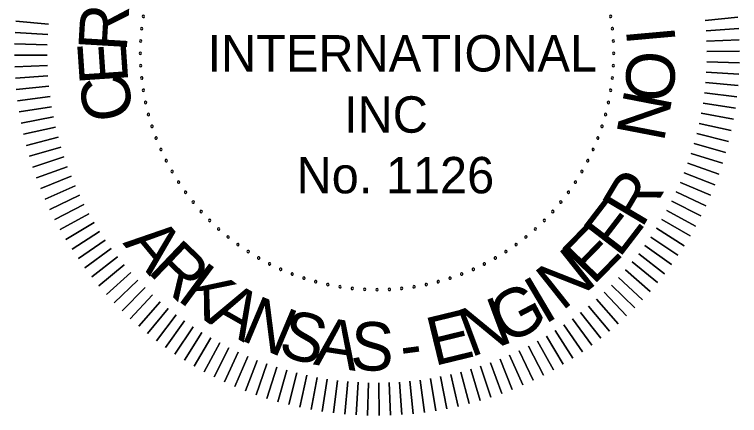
# Model space of a CAD drawing. Extents: x -712 to 3943, y 73 to 2823.
# Drawn here: x 2762.9 to 2970.3, y 202.1 to 316.9 of the extents above; entities that cross this region are included whole.
import ezdxf

# ---------------------------------------------------------------- set-up
doc = ezdxf.new("R2010")
doc.units = 0
doc.layers.add('G-ANNO-TEXT', color=7, linetype='Continuous')

msp = doc.modelspace()

# ---------------------------------------------------------------- linework, layer by layer
at = {"layer": 'G-ANNO-TEXT'}
for points in [[(2969.83, 316.1), (2960.53, 315.17)], [(2960.53, 315.17), (2969.83, 316.1)], [(2772.67, 314.12), (2763.35, 314.95)], [(2763.35, 314.95), (2772.67, 314.12)], [(2772.45, 311.16), (2763.12, 311.7)], [(2763.12, 311.7), (2772.45, 311.16)], [(2970.11, 312.85), (2960.78, 312.21)], [(2960.78, 312.21), (2970.11, 312.85)], [(2970.28, 309.6), (2960.93, 309.25)], [(2960.93, 309.25), (2970.28, 309.6)], [(2772.33, 308.2), (2762.98, 308.45)], [(2762.98, 308.45), (2772.33, 308.2)], [(2772.3, 305.24), (2762.95, 305.19)], [(2762.95, 305.19), (2772.3, 305.24)], [(2970.35, 306.34), (2961, 306.29)], [(2961, 306.29), (2970.35, 306.34)], [(2970.31, 303.09), (2960.97, 303.33)], [(2960.97, 303.33), (2970.31, 303.09)], [(2772.36, 302.28), (2763.02, 301.93)], [(2763.02, 301.93), (2772.36, 302.28)], [(2772.52, 299.32), (2763.19, 298.68)], [(2763.19, 298.68), (2772.52, 299.32)], [(2970.18, 299.83), (2960.84, 300.37)], [(2960.84, 300.37), (2970.18, 299.83)], [(2969.94, 296.58), (2960.63, 297.41)], [(2960.63, 297.41), (2969.94, 296.58)], [(2772.77, 296.36), (2763.46, 295.43)], [(2763.46, 295.43), (2772.77, 296.36)], [(2773.11, 293.42), (2763.84, 292.2)], [(2763.84, 292.2), (2773.11, 293.42)], [(2969.6, 293.34), (2960.32, 294.46)], [(2960.32, 294.46), (2969.6, 293.34)], [(2773.54, 290.49), (2764.32, 288.97)], [(2764.32, 288.97), (2773.54, 290.49)], [(2969.16, 290.11), (2959.92, 291.53)], [(2959.92, 291.53), (2969.16, 290.11)], [(2968.62, 286.9), (2959.42, 288.6)], [(2959.42, 288.6), (2968.62, 286.9)], [(2774.07, 287.57), (2764.89, 285.77)], [(2764.89, 285.77), (2774.07, 287.57)], [(2774.69, 284.67), (2765.57, 282.58)], [(2765.57, 282.58), (2774.69, 284.67)], [(2967.98, 283.71), (2958.84, 285.7)], [(2958.84, 285.7), (2967.98, 283.71)], [(2967.23, 280.54), (2958.16, 282.81)], [(2958.16, 282.81), (2967.23, 280.54)], [(2775.4, 281.79), (2766.35, 279.42)], [(2766.35, 279.42), (2775.4, 281.79)], [(2776.19, 278.94), (2767.23, 276.28)], [(2767.23, 276.28), (2776.19, 278.94)], [(2966.39, 277.39), (2957.4, 279.95)], [(2957.4, 279.95), (2966.39, 277.39)], [(2777.08, 276.11), (2768.2, 273.17)], [(2768.2, 273.17), (2777.08, 276.11)], [(2965.45, 274.27), (2956.54, 277.11)], [(2956.54, 277.11), (2965.45, 274.27)], [(2964.41, 271.18), (2955.6, 274.3)], [(2955.6, 274.3), (2964.41, 271.18)], [(2778.06, 273.31), (2769.28, 270.09)], [(2769.28, 270.09), (2778.06, 273.31)], [(2779.12, 270.55), (2770.44, 267.05)], [(2770.44, 267.05), (2779.12, 270.55)], [(2963.28, 268.13), (2954.56, 271.52)], [(2954.56, 271.52), (2963.28, 268.13)], [(2780.27, 267.81), (2771.71, 264.05)], [(2771.71, 264.05), (2780.27, 267.81)], [(2962.05, 265.11), (2953.45, 268.78)], [(2953.45, 268.78), (2962.05, 265.11)], [(2960.72, 262.14), (2952.24, 266.07)], [(2952.24, 266.07), (2960.72, 262.14)], [(2781.5, 265.12), (2773.06, 261.09)], [(2773.06, 261.09), (2781.5, 265.12)], [(2959.31, 259.2), (2950.95, 263.4)], [(2950.95, 263.4), (2959.31, 259.2)], [(2782.82, 262.46), (2774.51, 258.17)], [(2774.51, 258.17), (2782.82, 262.46)], [(2784.22, 259.85), (2776.05, 255.3)], [(2776.05, 255.3), (2784.22, 259.85)], [(2957.8, 256.31), (2949.58, 260.77)], [(2949.58, 260.77), (2957.8, 256.31)], [(2785.71, 257.29), (2777.68, 252.48)], [(2777.68, 252.48), (2785.71, 257.29)], [(2956.2, 253.48), (2948.12, 258.19)], [(2948.12, 258.19), (2956.2, 253.48)], [(2954.51, 250.69), (2946.59, 255.66)], [(2946.59, 255.66), (2954.51, 250.69)], [(2787.27, 254.77), (2779.4, 249.71)], [(2779.4, 249.71), (2787.27, 254.77)], [(2952.74, 247.96), (2944.98, 253.17)], [(2944.98, 253.17), (2952.74, 247.96)], [(2788.91, 252.3), (2781.21, 247)], [(2781.21, 247), (2788.91, 252.3)], [(2790.63, 249.88), (2783.09, 244.35)], [(2783.09, 244.35), (2790.63, 249.88)], [(2950.88, 245.28), (2943.29, 250.73)], [(2943.29, 250.73), (2950.88, 245.28)], [(2792.42, 247.52), (2785.06, 241.75)], [(2785.06, 241.75), (2792.42, 247.52)], [(2948.94, 242.66), (2941.52, 248.35)], [(2941.52, 248.35), (2948.94, 242.66)], [(2794.29, 245.22), (2787.12, 239.22)], [(2787.12, 239.22), (2794.29, 245.22)], [(2946.92, 240.11), (2939.68, 246.03)], [(2939.68, 246.03), (2946.92, 240.11)], [(2796.23, 242.98), (2789.24, 236.75)], [(2789.24, 236.75), (2796.23, 242.98)], [(2944.82, 237.62), (2937.77, 243.77)], [(2937.77, 243.77), (2944.82, 237.62)], [(2798.23, 240.8), (2791.45, 234.36)], [(2791.45, 234.36), (2798.23, 240.8)], [(2942.64, 235.2), (2935.78, 241.56)], [(2935.78, 241.56), (2942.64, 235.2)], [(2800.31, 238.68), (2793.73, 232.03)], [(2793.73, 232.03), (2800.31, 238.68)], [(2940.38, 232.85), (2933.73, 239.42)], [(2933.73, 239.42), (2940.38, 232.85)], [(2802.45, 236.63), (2796.08, 229.78)], [(2796.08, 229.78), (2802.45, 236.63)], [(2938.06, 230.57), (2931.62, 237.35)], [(2931.62, 237.35), (2938.06, 230.57)], [(2798.5, 227.6), (2804.65, 234.65)], [(2804.65, 234.65), (2798.5, 227.6)], [(2935.66, 228.36), (2929.44, 235.34)], [(2929.44, 235.34), (2935.66, 228.36)], [(2800.99, 225.5), (2806.91, 232.73)], [(2806.91, 232.73), (2800.99, 225.5)], [(2933.19, 226.23), (2927.19, 233.4)], [(2927.19, 233.4), (2933.19, 226.23)], [(2803.55, 223.47), (2809.24, 230.89)], [(2809.24, 230.89), (2803.55, 223.47)], [(2930.66, 224.18), (2924.89, 231.54)], [(2924.89, 231.54), (2930.66, 224.18)], [(2806.16, 221.53), (2811.62, 229.13)], [(2811.62, 229.13), (2806.16, 221.53)], [(2928.07, 222.21), (2922.53, 229.75)], [(2922.53, 229.75), (2928.07, 222.21)], [(2808.84, 219.67), (2814.05, 227.44)], [(2814.05, 227.44), (2808.84, 219.67)], [(2922.7, 218.52), (2917.65, 226.39)], [(2917.65, 226.39), (2922.7, 218.52)], [(2925.41, 220.32), (2920.11, 228.03)], [(2920.11, 228.03), (2925.41, 220.32)], [(2811.57, 217.9), (2816.54, 225.82)], [(2816.54, 225.82), (2811.57, 217.9)], [(2814.36, 216.21), (2819.07, 224.29)], [(2819.07, 224.29), (2814.36, 216.21)], [(2919.93, 216.8), (2915.13, 224.82)], [(2915.13, 224.82), (2919.93, 216.8)], [(2817.2, 214.61), (2821.66, 222.83)], [(2821.66, 222.83), (2817.2, 214.61)], [(2914.24, 213.63), (2909.95, 221.94)], [(2909.95, 221.94), (2914.24, 213.63)], [(2917.11, 215.17), (2912.56, 223.34)], [(2912.56, 223.34), (2917.11, 215.17)], [(2820.08, 213.11), (2824.28, 221.46)], [(2824.28, 221.46), (2820.08, 213.11)], [(2823.02, 211.69), (2826.95, 220.17)], [(2826.95, 220.17), (2823.02, 211.69)], [(2911.32, 212.18), (2907.3, 220.62)], [(2907.3, 220.62), (2911.32, 212.18)], [(2825.99, 210.37), (2829.66, 218.97)], [(2829.66, 218.97), (2825.99, 210.37)], [(2829.01, 209.14), (2832.41, 217.85)], [(2832.41, 217.85), (2829.01, 209.14)], [(2905.36, 209.56), (2901.87, 218.24)], [(2901.87, 218.24), (2905.36, 209.56)], [(2908.36, 210.82), (2904.6, 219.39)], [(2904.6, 219.39), (2908.36, 210.82)], [(2832.07, 208), (2835.18, 216.82)], [(2835.18, 216.82), (2832.07, 208)], [(2835.15, 206.96), (2837.99, 215.87)], [(2837.99, 215.87), (2835.15, 206.96)], [(2899.24, 207.32), (2896.3, 216.2)], [(2896.3, 216.2), (2899.24, 207.32)], [(2902.32, 208.39), (2899.1, 217.17)], [(2899.1, 217.17), (2902.32, 208.39)], [(2838.27, 206.02), (2840.83, 215.02)], [(2840.83, 215.02), (2838.27, 206.02)], [(2841.42, 205.18), (2843.69, 214.25)], [(2843.69, 214.25), (2841.42, 205.18)], [(2889.83, 204.69), (2887.74, 213.81)], [(2887.74, 213.81), (2889.83, 204.69)], [(2893, 205.47), (2890.62, 214.51)], [(2890.62, 214.51), (2893, 205.47)], [(2896.13, 206.34), (2893.48, 215.31)], [(2893.48, 215.31), (2896.13, 206.34)], [(2844.59, 204.44), (2846.58, 213.58)], [(2846.58, 213.58), (2844.59, 204.44)], [(2847.78, 203.79), (2849.49, 212.99)], [(2849.49, 212.99), (2847.78, 203.79)], [(2851, 203.25), (2852.41, 212.5)], [(2852.41, 212.5), (2851, 203.25)], [(2854.22, 202.81), (2855.35, 212.1)], [(2855.35, 212.1), (2854.22, 202.81)], [(2857.46, 202.47), (2858.29, 211.79)], [(2858.29, 211.79), (2857.46, 202.47)], [(2860.71, 202.23), (2861.25, 211.57)], [(2861.25, 211.57), (2860.71, 202.23)], [(2873.74, 202.31), (2873.1, 211.64)], [(2873.1, 211.64), (2873.74, 202.31)], [(2876.98, 202.58), (2876.05, 211.89)], [(2876.05, 211.89), (2876.98, 202.58)], [(2880.22, 202.96), (2878.99, 212.23)], [(2878.99, 212.23), (2880.22, 202.96)], [(2883.44, 203.43), (2881.93, 212.66)], [(2881.93, 212.66), (2883.44, 203.43)], [(2886.65, 204.01), (2884.84, 213.19)], [(2884.84, 213.19), (2886.65, 204.01)], [(2863.97, 202.1), (2864.21, 211.45)], [(2864.21, 211.45), (2863.97, 202.1)], [(2867.23, 202.07), (2867.17, 211.42)], [(2867.17, 211.42), (2867.23, 202.07)], [(2870.48, 202.14), (2870.14, 211.48)], [(2870.14, 211.48), (2870.48, 202.14)]]:
    msp.add_lwpolyline(points, dxfattribs=at)
for centre, start, end in [((2799.8, 316.35), 81, 261), ((2799.8, 316.35), 261, 81), ((2933.49, 316.35), 99, 279), ((2933.49, 316.35), 279, 99), ((2799.34, 312.84), 84, 264), ((2799.34, 312.84), 264, 84), ((2933.96, 312.84), 96, 276), ((2933.96, 312.84), 276, 96), ((2799.06, 309.31), 87, 267), ((2799.06, 309.31), 267, 87), ((2934.23, 309.31), 93, 273), ((2934.23, 309.31), 273, 93), ((2798.97, 305.77), 90, 270), ((2798.97, 305.77), 270, 90), ((2934.33, 305.77), 90, 270), ((2934.33, 305.77), 270, 90), ((2799.06, 302.22), 93, 273), ((2799.06, 302.22), 273, 93), ((2934.23, 302.22), 87, 267), ((2934.23, 302.22), 267, 87), ((2799.34, 298.69), 96, 276), ((2799.34, 298.69), 276, 96), ((2933.96, 298.69), 84, 264), ((2933.96, 298.69), 264, 84), ((2799.8, 295.18), 99, 279), ((2799.8, 295.18), 279, 99), ((2933.49, 295.18), 81, 261), ((2933.49, 295.18), 261, 81), ((2800.45, 291.69), 102, 282), ((2800.45, 291.69), 282, 102), ((2932.85, 291.69), 78, 258), ((2932.85, 291.69), 258, 78), ((2801.28, 288.25), 105, 285), ((2801.28, 288.25), 285, 105), ((2932.02, 288.25), 75, 255), ((2932.02, 288.25), 255, 75), ((2802.28, 284.85), 108, 288), ((2802.28, 284.85), 288, 108), ((2931.02, 284.85), 72, 252), ((2931.02, 284.85), 252, 72), ((2803.46, 281.51), 111, 291), ((2803.46, 281.51), 291, 111), ((2929.83, 281.51), 69, 249), ((2929.83, 281.51), 249, 69), ((2804.82, 278.24), 114, 294), ((2804.82, 278.24), 294, 114), ((2928.48, 278.24), 66, 246), ((2928.48, 278.24), 246, 66), ((2806.35, 275.04), 117, 297), ((2806.35, 275.04), 297, 117), ((2926.95, 275.04), 63, 243), ((2926.95, 275.04), 243, 63), ((2808.04, 271.93), 120, 300), ((2808.04, 271.93), 300, 120), ((2925.26, 271.93), 60, 240), ((2925.26, 271.93), 240, 60), ((2809.89, 268.9), 123, 303), ((2809.89, 268.9), 303, 123), ((2923.41, 268.9), 57, 237), ((2923.41, 268.9), 237, 57), ((2811.9, 265.98), 126, 306), ((2811.9, 265.98), 306, 126), ((2921.4, 265.98), 54, 234), ((2921.4, 265.98), 234, 54), ((2814.05, 263.17), 129, 309), ((2814.05, 263.17), 309, 129), ((2919.24, 263.17), 51, 231), ((2919.24, 263.17), 231, 51), ((2816.35, 260.48), 132, 312), ((2816.35, 260.48), 312, 132), ((2916.94, 260.48), 48, 228), ((2916.94, 260.48), 228, 48), ((2818.79, 257.91), 135, 315), ((2818.79, 257.91), 315, 135), ((2914.5, 257.91), 45, 225), ((2914.5, 257.91), 225, 45), ((2821.36, 255.47), 138, 318), ((2821.36, 255.47), 318, 138), ((2911.93, 255.47), 42, 222), ((2911.93, 255.47), 222, 42), ((2824.06, 253.17), 141, 321), ((2824.06, 253.17), 321, 141), ((2909.24, 253.17), 39, 219), ((2909.24, 253.17), 219, 39), ((2826.87, 251.01), 144, 324), ((2826.87, 251.01), 324, 144), ((2906.43, 251.01), 36, 216), ((2906.43, 251.01), 216, 36), ((2829.79, 249.01), 147, 327), ((2829.79, 249.01), 327, 147), ((2903.51, 249.01), 33, 213), ((2903.51, 249.01), 213, 33), ((2832.81, 247.15), 150, 330), ((2832.81, 247.15), 330, 150), ((2900.49, 247.15), 30, 210), ((2900.49, 247.15), 210, 30), ((2835.92, 245.46), 153, 333), ((2835.92, 245.46), 333, 153), ((2897.37, 245.46), 27, 207), ((2897.37, 245.46), 207, 27), ((2839.12, 243.94), 156, 336), ((2839.12, 243.94), 336, 156), ((2842.39, 242.58), 159, 339), ((2842.39, 242.58), 339, 159), ((2890.9, 242.58), 21, 201), ((2890.9, 242.58), 201, 21), ((2894.18, 243.94), 24, 204), ((2894.18, 243.94), 204, 24), ((2845.73, 241.4), 162, 342), ((2845.73, 241.4), 342, 162), ((2849.13, 240.39), 345, 165), ((2884.17, 240.39), 15, 195), ((2887.56, 241.4), 18, 198), ((2887.56, 241.4), 198, 18), ((2849.13, 240.39), 165, 345), ((2852.58, 239.57), 168, 348), ((2852.58, 239.57), 348, 168), ((2856.06, 238.92), 171, 351), ((2856.06, 238.92), 351, 171), ((2859.57, 238.46), 354, 174), ((2863.11, 238.18), 357, 177), ((2870.19, 238.18), 3, 183), ((2873.72, 238.46), 6, 186), ((2877.24, 238.92), 9, 189), ((2877.24, 238.92), 189, 9), ((2880.72, 239.57), 12, 192), ((2880.72, 239.57), 192, 12), ((2884.17, 240.39), 195, 15), ((2859.57, 238.46), 174, 354), ((2863.11, 238.18), 177, 357), ((2866.65, 238.09), 0, 180), ((2866.65, 238.09), 180, 0), ((2870.19, 238.18), 183, 3), ((2873.72, 238.46), 186, 6)]:
    msp.add_arc(centre, 0.347, start, end, dxfattribs=at)

# ---------------------------------------------------------------- texts
for s, rotation, p in [('R', 86.6268, (2795.03, 306.07)), ('I', 275.1216, (2937.82, 312.77)), ('E', 93.9203, (2795.54, 297.4)), ('O', 267.0743, (2938.31, 306.8)), ('C', 101.2137, (2797.32, 287.74)), ('N', 259.0269, (2937.58, 295.88)), ('R', 59.2262, (2942.37, 255.4)), ('E', 52.4765, (2935.93, 246.85)), ('A', 309.5859, (2793.76, 251.38)), ('E', 45.7268, (2928.52, 239.11)), ('R', 316.3356, (2800.66, 243.19)), ('N', 38.4196, (2919.54, 231.79)), ('K', 323.6428, (2809.15, 235.3)), ('I', 30.5495, (2914.5, 227.96)), ('A', 330.3925, (2817.83, 229.03)), ('G', 27.7404, (2903.52, 222.13)), ('N', 337.1422, (2827.19, 223.83)), ('N', 20.4332, (2893.4, 218.63)), ('E', 13.6835, (2882.94, 216.18)), ('S', 344.4494, (2837.93, 219.48)), ('A', 351.1991, (2848.27, 216.7)), ('S', 357.9489, (2858.87, 215.16)), ('-', 7.5077, (2874.02, 215.12))]:
    msp.add_text(s, height=13.89, rotation=rotation, dxfattribs=at).set_placement(p)
for s, p in [(' INTERNATIONAL', (2814.28, 300.56)), ('INC', (2857.21, 283.04)), (' No. 1126', (2839.76, 265.68))]:
    msp.add_text(s, height=10.418, dxfattribs=at).set_placement(p)

doc.saveas('drawing.dxf')
